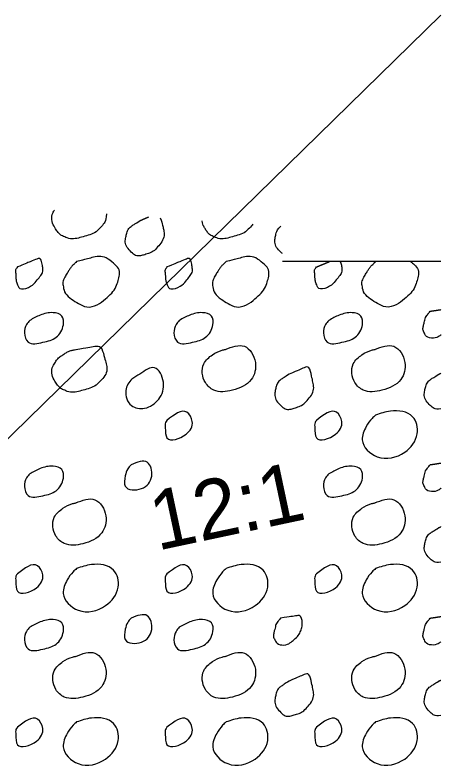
# Model space of a CAD drawing. Extents: x -1577 to 2037, y 0 to 220.
# Drawn here: x 87.67 to 97.74, y 132.4 to 150.21 of the extents above; entities that cross this region are included whole.
import ezdxf

# ---------------------------------------------------------------- set-up
doc = ezdxf.new("R2010")
doc.units = 0
for name, color, linetype in [('DR_P_Culvert', 7, 'Continuous'), ('GE_P_Alignment_100_Stations', 7, 'Continuous'), ('XS_P_Pavt_Surface', 7, 'Continuous')]:
    doc.layers.add(name, color=color, linetype=linetype)

msp = doc.modelspace()

# ---------------------------------------------------------------- linework, layer by layer
at = {"layer": 'DR_P_Culvert'}
msp.add_line((97.737, 144.378), (93.987, 144.378), dxfattribs=at)
at = {"layer": 'GE_P_Alignment_100_Stations'}
msp.add_line((97.737, 150.211), (70.83, 123.877), dxfattribs=at)
at = {"layer": 'XS_P_Pavt_Surface'}
for points, degree in [([(89.827, 145.504), (89.826, 145.405), (89.792, 145.302), (89.715, 145.217), (89.582, 145.069), (89.434, 145.012), (89.27, 144.964), (89.128, 144.922), (88.97, 144.907), (88.83, 144.967), (88.744, 145.002), (88.682, 145.065), (88.63, 145.145), (88.544, 145.279), (88.518, 145.463), (88.594, 145.59), (88.594, 145.59), (88.594, 145.591), (88.595, 145.591)], 3), ([(91.095, 145.415), (91.134, 145.337), (91.159, 145.226), (91.174, 145.157), (91.202, 145.026), (91.168, 144.879), (91.062, 144.752), (90.962, 144.633), (90.849, 144.576), (90.729, 144.54), (90.633, 144.511), (90.512, 144.506), (90.418, 144.599), (90.304, 144.711), (90.262, 144.844), (90.285, 144.958), (90.303, 145.049), (90.345, 145.169), (90.43, 145.226), (90.492, 145.266), (90.553, 145.305), (90.615, 145.345)], 3), ([(90.615, 145.345), (90.684, 145.375), (90.753, 145.404), (90.823, 145.434)], 2), ([(93.286, 145.26), (93.276, 145.245), (93.264, 145.231), (93.251, 145.217), (93.118, 145.069), (92.97, 145.012), (92.805, 144.964), (92.664, 144.922), (92.506, 144.907), (92.365, 144.967), (92.28, 145.002), (92.218, 145.065), (92.166, 145.145), (92.128, 145.205), (92.101, 145.274), (92.09, 145.345)], 3), ([(93.987, 144.571), (93.976, 144.579), (93.965, 144.588), (93.954, 144.599), (93.84, 144.711), (93.798, 144.844), (93.82, 144.958), (93.837, 145.043), (93.876, 145.153), (93.95, 145.214)], 3), ([(89.12, 144.376), (89.238, 144.407), (89.357, 144.438), (89.475, 144.469), (89.649, 144.514), (89.823, 144.482), (89.996, 144.337), (90.131, 144.225), (90.139, 144.059), (90.104, 143.935), (90.059, 143.778), (89.96, 143.63), (89.808, 143.5), (89.618, 143.338), (89.354, 143.274), (89.16, 143.389), (89.002, 143.482), (88.836, 143.622), (88.805, 143.787), (88.786, 143.89), (88.84, 144.01), (88.9, 144.106), (88.944, 144.174), (88.982, 144.243), (89.039, 144.298), (89.066, 144.324), (89.093, 144.35), (89.12, 144.376)], 3), ([(92.655, 144.376), (92.774, 144.407), (92.893, 144.438), (93.011, 144.469), (93.184, 144.514), (93.359, 144.482), (93.532, 144.337), (93.666, 144.225), (93.675, 144.059), (93.64, 143.935), (93.595, 143.778), (93.496, 143.63), (93.344, 143.5), (93.154, 143.338), (92.89, 143.274), (92.695, 143.389), (92.538, 143.482), (92.372, 143.622), (92.341, 143.787), (92.322, 143.89), (92.376, 144.01), (92.436, 144.106), (92.479, 144.174), (92.518, 144.243), (92.575, 144.298), (92.601, 144.324), (92.628, 144.35), (92.655, 144.376)], 3), ([(87.72, 144.25), (87.879, 144.314), (88.037, 144.382), (88.195, 144.442), (88.273, 144.472), (88.314, 144.298), (88.321, 144.224), (88.331, 144.124), (88.254, 144.02), (88.172, 143.922), (88.061, 143.787), (87.78, 143.69), (87.722, 143.837), (87.691, 143.916), (87.686, 143.996), (87.683, 144.077), (87.681, 144.118), (87.666, 144.162), (87.687, 144.198), (87.698, 144.216), (87.71, 144.233), (87.72, 144.25)], 3), ([(91.256, 144.25), (91.415, 144.314), (91.573, 144.382), (91.731, 144.442), (91.809, 144.472), (91.85, 144.298), (91.857, 144.224), (91.866, 144.124), (91.79, 144.02), (91.708, 143.922), (91.596, 143.787), (91.316, 143.69), (91.258, 143.837), (91.227, 143.916), (91.222, 143.996), (91.219, 144.077), (91.217, 144.118), (91.202, 144.162), (91.223, 144.198), (91.234, 144.216), (91.245, 144.233), (91.256, 144.25)], 3), ([(95.354, 144.378), (95.377, 144.328), (95.389, 144.263), (95.393, 144.224), (95.402, 144.124), (95.326, 144.02), (95.244, 143.922), (95.132, 143.787), (94.852, 143.69), (94.794, 143.837), (94.763, 143.916), (94.758, 143.996), (94.755, 144.077), (94.753, 144.118), (94.738, 144.162), (94.759, 144.198), (94.769, 144.216), (94.781, 144.233), (94.792, 144.25)], 3), ([(94.792, 144.25), (94.896, 144.292), (94.999, 144.335), (95.103, 144.378)], 2), ([(97.016, 144.378), (97.033, 144.365), (97.051, 144.352), (97.068, 144.337), (97.202, 144.225), (97.211, 144.059), (97.175, 143.935), (97.13, 143.778), (97.032, 143.63), (96.88, 143.5), (96.69, 143.338), (96.426, 143.274), (96.231, 143.389), (96.074, 143.482), (95.907, 143.622), (95.877, 143.787), (95.858, 143.89), (95.912, 144.01), (95.972, 144.106), (96.015, 144.174), (96.054, 144.243), (96.11, 144.298), (96.137, 144.324), (96.164, 144.35), (96.191, 144.376)], 3), ([(96.191, 144.376), (96.194, 144.376), (96.196, 144.377), (96.198, 144.378)], 2), ([(97.482, 143.203), (97.567, 143.215), (97.652, 143.228), (97.737, 143.241)], 2), ([(97.737, 142.643), (97.734, 142.641), (97.731, 142.638), (97.728, 142.636), (97.623, 142.556), (97.402, 142.569), (97.341, 142.693), (97.303, 142.77), (97.322, 142.861), (97.344, 142.939), (97.359, 142.993), (97.366, 143.056), (97.402, 143.102), (97.429, 143.136), (97.455, 143.169), (97.482, 143.203)], 3), ([(89.099, 142.297), (89.25, 142.323), (89.402, 142.352), (89.553, 142.373), (89.704, 142.394), (89.774, 142.135), (89.812, 141.993), (89.847, 141.864), (89.824, 141.706), (89.715, 141.586), (89.582, 141.439), (89.434, 141.382), (89.27, 141.334), (89.128, 141.292), (88.97, 141.277), (88.83, 141.336), (88.744, 141.372), (88.682, 141.434), (88.63, 141.514), (88.544, 141.648), (88.518, 141.833), (88.594, 141.959), (88.644, 142.043), (88.712, 142.117), (88.799, 142.173), (88.872, 142.22), (88.943, 142.264), (89.025, 142.281), (89.052, 142.287), (89.08, 142.293), (89.107, 142.299)], 3), ([(94.15, 141.714), (94.268, 141.765), (94.385, 141.815), (94.502, 141.865), (94.624, 141.917), (94.683, 141.651), (94.71, 141.527), (94.738, 141.396), (94.704, 141.249), (94.598, 141.122), (94.498, 141.002), (94.384, 140.946), (94.265, 140.909), (94.169, 140.88), (94.048, 140.876), (93.954, 140.969), (93.84, 141.081), (93.798, 141.213), (93.82, 141.328), (93.839, 141.419), (93.881, 141.539), (93.966, 141.595), (94.028, 141.636), (94.089, 141.674), (94.15, 141.714)], 3), ([(97.737, 140.895), (97.655, 140.883), (97.564, 140.895), (97.49, 140.969), (97.376, 141.081), (97.333, 141.213), (97.356, 141.328), (97.374, 141.419), (97.417, 141.539), (97.502, 141.595), (97.563, 141.636), (97.625, 141.674), (97.686, 141.714)], 3), ([(97.686, 141.714), (97.703, 141.722), (97.72, 141.729), (97.737, 141.736)], 2), ([(97.737, 139.013), (97.734, 139.01), (97.731, 139.008), (97.728, 139.006), (97.623, 138.925), (97.402, 138.939), (97.341, 139.062), (97.303, 139.14), (97.322, 139.23), (97.344, 139.308), (97.359, 139.363), (97.366, 139.426), (97.402, 139.471), (97.429, 139.505), (97.455, 139.539), (97.482, 139.572)], 3), ([(97.482, 139.572), (97.567, 139.584), (97.652, 139.598), (97.737, 139.61)], 2), ([(97.737, 137.264), (97.655, 137.252), (97.564, 137.265), (97.49, 137.338), (97.376, 137.45), (97.333, 137.583), (97.356, 137.697), (97.374, 137.788), (97.417, 137.908), (97.502, 137.965), (97.563, 138.005), (97.625, 138.044), (97.686, 138.084)], 3), ([(97.686, 138.084), (97.703, 138.091), (97.72, 138.098), (97.737, 138.106)], 2), ([(93.946, 135.942), (94.074, 135.96), (94.201, 135.98), (94.328, 135.998), (94.442, 136.013), (94.468, 135.768), (94.432, 135.669), (94.393, 135.561), (94.294, 135.453), (94.192, 135.375), (94.087, 135.295), (93.866, 135.308), (93.805, 135.432), (93.767, 135.51), (93.786, 135.6), (93.808, 135.678), (93.823, 135.733), (93.83, 135.796), (93.866, 135.841), (93.893, 135.875), (93.92, 135.908), (93.946, 135.942)], 3), ([(97.737, 135.382), (97.734, 135.38), (97.731, 135.377), (97.728, 135.375), (97.623, 135.295), (97.402, 135.308), (97.341, 135.432), (97.303, 135.51), (97.322, 135.6), (97.344, 135.678), (97.359, 135.733), (97.366, 135.796), (97.402, 135.841), (97.429, 135.875), (97.455, 135.908), (97.482, 135.942)], 3), ([(97.482, 135.942), (97.567, 135.954), (97.652, 135.967), (97.737, 135.98)], 2), ([(94.15, 134.453), (94.268, 134.504), (94.385, 134.554), (94.502, 134.604), (94.624, 134.656), (94.683, 134.39), (94.71, 134.266), (94.738, 134.135), (94.704, 133.988), (94.598, 133.861), (94.498, 133.741), (94.384, 133.685), (94.265, 133.648), (94.169, 133.619), (94.048, 133.615), (93.954, 133.708), (93.84, 133.82), (93.798, 133.952), (93.82, 134.067), (93.839, 134.158), (93.881, 134.278), (93.966, 134.334), (94.028, 134.375), (94.089, 134.413), (94.15, 134.453)], 3), ([(97.737, 133.634), (97.655, 133.622), (97.564, 133.634), (97.49, 133.708), (97.376, 133.82), (97.333, 133.952), (97.356, 134.067), (97.374, 134.158), (97.417, 134.278), (97.502, 134.334), (97.563, 134.375), (97.625, 134.413), (97.686, 134.453)], 3), ([(97.686, 134.453), (97.703, 134.461), (97.72, 134.468), (97.737, 134.475)], 2)]:
    msp.add_open_spline(points, degree=degree, dxfattribs=at)
for points in [[(88.012, 142.986), (88.262, 143.111), (88.563, 143.169), (88.774, 143.088), (88.808, 142.884), (88.637, 142.588), (88.324, 142.468), (87.972, 142.474), (87.886, 142.689), (87.938, 142.889), (88.012, 142.986)], [(91.548, 142.986), (91.798, 143.111), (92.099, 143.169), (92.31, 143.088), (92.344, 142.884), (92.173, 142.588), (91.86, 142.468), (91.508, 142.474), (91.422, 142.689), (91.474, 142.889), (91.548, 142.986)], [(95.084, 142.986), (95.334, 143.111), (95.635, 143.169), (95.845, 143.088), (95.88, 142.884), (95.709, 142.588), (95.395, 142.468), (95.044, 142.474), (94.958, 142.689), (95.01, 142.889), (95.084, 142.986)], [(92.635, 142.297), (93.089, 142.373), (93.348, 141.993), (93.251, 141.586), (92.805, 141.334), (92.365, 141.336), (92.166, 141.514), (92.13, 141.959), (92.335, 142.173), (92.56, 142.281), (92.643, 142.299)], [(96.17, 142.297), (96.625, 142.373), (96.884, 141.993), (96.787, 141.586), (96.341, 141.334), (95.901, 141.336), (95.702, 141.514), (95.665, 141.959), (95.87, 142.173), (96.096, 142.281), (96.179, 142.299)], [(90.615, 141.714), (90.966, 141.865), (91.174, 141.527), (91.062, 141.122), (90.729, 140.909), (90.418, 140.969), (90.285, 141.328), (90.43, 141.595), (90.615, 141.714)], [(91.256, 140.619), (91.731, 140.812), (91.857, 140.594), (91.708, 140.291), (91.258, 140.207), (91.219, 140.447), (91.223, 140.568), (91.256, 140.619)], [(94.792, 140.619), (95.267, 140.812), (95.393, 140.594), (95.244, 140.291), (94.794, 140.207), (94.755, 140.447), (94.759, 140.568), (94.792, 140.619)], [(96.191, 140.745), (96.547, 140.839), (97.068, 140.707), (97.175, 140.304), (96.88, 139.869), (96.231, 139.759), (95.877, 140.157), (95.972, 140.475), (96.11, 140.668), (96.191, 140.745)], [(90.41, 139.572), (90.792, 139.628), (90.896, 139.3), (90.656, 139.006), (90.27, 139.062), (90.272, 139.308), (90.33, 139.471), (90.41, 139.572)], [(88.012, 139.356), (88.262, 139.481), (88.563, 139.538), (88.774, 139.457), (88.808, 139.254), (88.637, 138.957), (88.324, 138.837), (87.972, 138.843), (87.886, 139.059), (87.938, 139.259), (88.012, 139.356)], [(95.084, 139.356), (95.334, 139.481), (95.635, 139.538), (95.845, 139.457), (95.88, 139.254), (95.709, 138.957), (95.395, 138.837), (95.044, 138.843), (94.958, 139.059), (95.01, 139.259), (95.084, 139.356)], [(89.099, 138.666), (89.553, 138.742), (89.812, 138.362), (89.715, 137.956), (89.27, 137.703), (88.83, 137.706), (88.63, 137.884), (88.594, 138.329), (88.799, 138.542), (89.025, 138.651), (89.107, 138.668)], [(96.17, 138.666), (96.625, 138.742), (96.884, 138.362), (96.787, 137.956), (96.341, 137.703), (95.901, 137.706), (95.702, 137.884), (95.665, 138.329), (95.87, 138.542), (96.096, 138.651), (96.179, 138.668)], [(87.72, 136.989), (88.195, 137.181), (88.321, 136.963), (88.172, 136.661), (87.722, 136.576), (87.683, 136.816), (87.687, 136.937), (87.72, 136.989)], [(89.12, 137.115), (89.475, 137.208), (89.996, 137.076), (90.104, 136.674), (89.808, 136.239), (89.16, 136.128), (88.805, 136.526), (88.9, 136.845), (89.039, 137.037), (89.12, 137.115)], [(91.256, 136.989), (91.731, 137.181), (91.857, 136.963), (91.708, 136.661), (91.258, 136.576), (91.219, 136.816), (91.223, 136.937), (91.256, 136.989)], [(92.655, 137.115), (93.011, 137.208), (93.532, 137.076), (93.64, 136.674), (93.344, 136.239), (92.695, 136.128), (92.341, 136.526), (92.436, 136.845), (92.575, 137.037), (92.655, 137.115)], [(94.792, 136.989), (95.267, 137.181), (95.393, 136.963), (95.244, 136.661), (94.794, 136.576), (94.755, 136.816), (94.759, 136.937), (94.792, 136.989)], [(96.191, 137.115), (96.547, 137.208), (97.068, 137.076), (97.175, 136.674), (96.88, 136.239), (96.231, 136.128), (95.877, 136.526), (95.972, 136.845), (96.11, 137.037), (96.191, 137.115)], [(90.41, 135.942), (90.792, 135.998), (90.896, 135.669), (90.656, 135.375), (90.27, 135.432), (90.272, 135.678), (90.33, 135.841), (90.41, 135.942)], [(88.012, 135.725), (88.262, 135.85), (88.563, 135.908), (88.774, 135.827), (88.808, 135.623), (88.637, 135.327), (88.324, 135.207), (87.972, 135.213), (87.886, 135.428), (87.938, 135.628), (88.012, 135.725)], [(91.548, 135.725), (91.798, 135.85), (92.099, 135.908), (92.31, 135.827), (92.344, 135.623), (92.173, 135.327), (91.86, 135.207), (91.508, 135.213), (91.422, 135.428), (91.474, 135.628), (91.548, 135.725)], [(89.099, 135.036), (89.553, 135.112), (89.812, 134.732), (89.715, 134.325), (89.27, 134.073), (88.83, 134.075), (88.63, 134.253), (88.594, 134.698), (88.799, 134.912), (89.025, 135.02), (89.107, 135.038)], [(92.635, 135.036), (93.089, 135.112), (93.348, 134.732), (93.251, 134.325), (92.805, 134.073), (92.365, 134.075), (92.166, 134.253), (92.13, 134.698), (92.335, 134.912), (92.56, 135.02), (92.643, 135.038)], [(96.17, 135.036), (96.625, 135.112), (96.884, 134.732), (96.787, 134.325), (96.341, 134.073), (95.901, 134.075), (95.702, 134.253), (95.665, 134.698), (95.87, 134.912), (96.096, 135.02), (96.179, 135.038)], [(87.72, 133.358), (88.195, 133.551), (88.321, 133.333), (88.172, 133.03), (87.722, 132.946), (87.683, 133.186), (87.687, 133.307), (87.72, 133.358)], [(91.256, 133.358), (91.731, 133.551), (91.857, 133.333), (91.708, 133.03), (91.258, 132.946), (91.219, 133.186), (91.223, 133.307), (91.256, 133.358)], [(94.792, 133.358), (95.267, 133.551), (95.393, 133.333), (95.244, 133.03), (94.794, 132.946), (94.755, 133.186), (94.759, 133.307), (94.792, 133.358)], [(89.12, 133.484), (89.475, 133.578), (89.996, 133.446), (90.104, 133.043), (89.808, 132.608), (89.16, 132.498), (88.805, 132.896), (88.9, 133.214), (89.039, 133.407), (89.12, 133.484)], [(92.655, 133.484), (93.011, 133.578), (93.532, 133.446), (93.64, 133.043), (93.344, 132.608), (92.695, 132.498), (92.341, 132.896), (92.436, 133.214), (92.575, 133.407), (92.655, 133.484)], [(96.191, 133.484), (96.547, 133.578), (97.068, 133.446), (97.175, 133.043), (96.88, 132.608), (96.231, 132.498), (95.877, 132.896), (95.972, 133.214), (96.11, 133.407), (96.191, 133.484)]]:
    msp.add_spline(points, degree=3, dxfattribs=at)

# ---------------------------------------------------------------- texts
at = {"layer": 'GE_P_Alignment_100_Stations'}
msp.add_text('12:1', height=1.4, rotation=11.9922, dxfattribs=at).set_placement((91.028, 137.535))

doc.saveas('drawing.dxf')
